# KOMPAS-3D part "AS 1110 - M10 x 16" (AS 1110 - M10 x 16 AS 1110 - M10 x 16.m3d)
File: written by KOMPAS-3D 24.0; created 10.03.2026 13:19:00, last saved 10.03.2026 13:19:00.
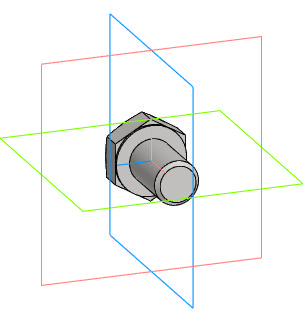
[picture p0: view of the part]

Document properties: Автор: R2D2; Полное имя файла: E:\Работа\Зайцев\BV3232P(4pc)-FP-3WL-F-ISO-H Кран шаровой DN.ru Ду15-100 Ру16\DN100\исходные материалы\AS 1110 - M10 x 16 AS 1110 - M10 x 16.m3d

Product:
- Body: Solid1  | qty 1
- Part/product: AS 1110 - M10 x 16
    Комментарий: Болты и винты   шестигранные точные   метрические ISO
    additional columns: Сталь, мягкая

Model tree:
1. Solid1  (labels: Solid1)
